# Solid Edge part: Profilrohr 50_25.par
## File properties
Author: ahadarics
Last saved by: ahadarics
Revision: 77
Sűrűség: 0,000 kg/m^3
Pontosság: 0,990
Username: ahadarics
Dokumentum tartalom típus: 0
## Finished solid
Body 1: solid body, 175 faces, 519 edges, 346 vertices.
  Faces by surface: cylinder 107, plane 68
  Edges by curve: line 305, circle 214
Bounding box of the edges (mm): 60.200 x 60.200 x 69.000, from (-30.1, -30.1, -34.5) to (30.1, 30.1, 34.5).
Cylindrical faces by radius (mm): R0.1 x16, R0.2 x30, R0.5 x28, R1 x8, R3.75 x8, R5 x4, R6 x4, R25 x1, R27 x8
Planar faces by outward normal: +x 6, +y 6, +z 1, -x 4, -y 4, -z 1, oblique 46
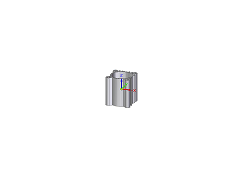
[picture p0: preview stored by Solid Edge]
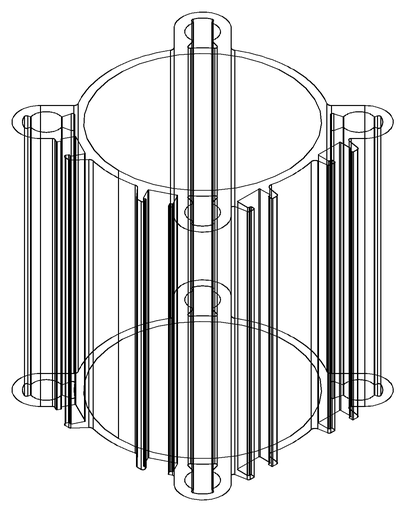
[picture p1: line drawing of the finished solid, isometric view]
